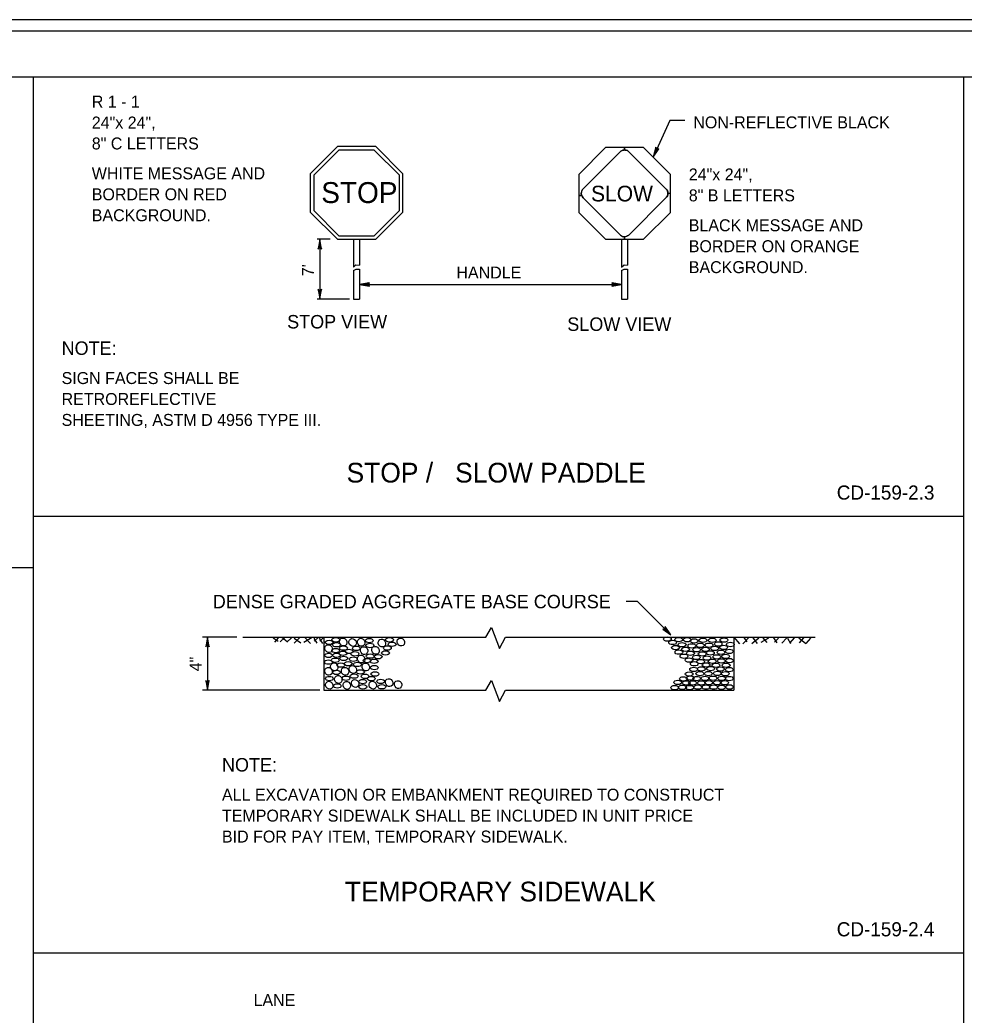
# Model space of a CAD drawing. Extents: x 499940 to 501012, y 499990 to 500649.
# Drawn here: x 500335 to 500650.7, y 500316.4 to 500649.2 of the extents above; entities that cross this region are included whole.
import ezdxf

# ---------------------------------------------------------------- set-up
doc = ezdxf.new("R2010")
doc.units = 0
for name, color, linetype in [('1', 7, 'Continuous'), ('10', 7, 'Continuous'), ('24', 7, 'Continuous'), ('3', 7, 'Continuous'), ('41', 7, 'Continuous'), ('5', 7, 'Continuous'), ('56', 7, 'Continuous'), ('57', 7, 'Continuous'), ('60', 7, 'Continuous')]:
    doc.layers.add(name, color=color, linetype=linetype)

msp = doc.modelspace()

# ---------------------------------------------------------------- linework, layer by layer
at = {"layer": '1'}
for p, q in [((500990, 500630), (500000, 500630)), ((500407.51, 500442.8), (500396.01, 500442.8)), ((500397.71, 500442.8), (500397.71, 500425.08)), ((500409.5, 500442.8), (500490.79, 500442.8)), ((500419.72, 500442.59), (500421.34, 500441.4)), ((500421.34, 500442.59), (500420.1, 500441.14)), ((500423.6, 500442.64), (500422.04, 500441.19)), ((500422.73, 500442.64), (500424.4, 500441.35)), ((500425.85, 500442.59), (500424.24, 500441.08)), ((500428.7, 500442.75), (500426.66, 500440.81)), ((500426.71, 500442.48), (500428.87, 500440.92)), ((500432.68, 500442.64), (500429.89, 500441.03)), ((500430.32, 500442.59), (500432.2, 500440.65)), ((500433.28, 500442.48), (500434.3, 500440.76)), ((500434.62, 500442.59), (500433.33, 500441.4)), ((500435, 500442.48), (500436.13, 500440.65)), ((500436.66, 500442.8), (500435.32, 500441.46)), ((500436.66, 500442.8), (500436.66, 500425.08)), ((500497.31, 500442.8), (500600.84, 500442.8)), ((500573.67, 500442.8), (500573.67, 500425.08)), ((500573.67, 500442.8), (500575.59, 500440.59)), ((500578.56, 500442.58), (500576.66, 500440.51)), ((500577.04, 500442.65), (500578.03, 500441.2)), ((500582.08, 500442.5), (500579.71, 500440.51)), ((500580.01, 500442.58), (500581.46, 500440.67)), ((500585.28, 500442.5), (500582.76, 500440.97)), ((500583.3, 500442.65), (500584.75, 500440.97)), ((500586.96, 500442.58), (500588.11, 500440.9)), ((500588.64, 500442.42), (500587.27, 500441.12)), ((500591.46, 500442.58), (500589.78, 500440.82)), ((500591.62, 500442.5), (500592.61, 500440.67)), ((500593.83, 500442.58), (500592.38, 500440.9)), ((500595.43, 500442.58), (500597.72, 500440.67)), ((500597.04, 500442.58), (500595.59, 500440.9)), ((500599.33, 500442.5), (500597.8, 500440.67)), ((500435.32, 500425.08), (500396.01, 500425.08)), ((500436.66, 500425.08), (500490.79, 500425.08)), ((500497.31, 500425.08), (500573.67, 500425.08))]:
    msp.add_line(p, q, dxfattribs=at)
for points in [[(499956.44, 500645.46), (500590.04, 500645.46), (501001.61, 500645.46)], [(500490.79, 500442.8), (500492.71, 500446), (500495.29, 500439.03), (500497.31, 500442.8)], [(500490.79, 500425.08), (500492.71, 500428.29), (500495.29, 500421.31), (500497.31, 500425.08)]]:
    msp.add_lwpolyline(points, dxfattribs=at)
for centre in [(500438.4, 500441.05), (500440.61, 500441.9), (500440.84, 500440.24), (500451.8, 500441.66), (500452.01, 500440.01), (500458.56, 500441.9), (500459.42, 500440.41), (500551.47, 500442.15), (500553.23, 500441.02), (500555.27, 500441.98), (500556.4, 500440.28), (500558.1, 500441.92), (500559.62, 500439.89), (500560.42, 500441.53), (500562.51, 500440.06), (500563.36, 500441.75), (500565.4, 500440.11), (500566.47, 500441.75), (500568.51, 500440.51), (500570.38, 500441.81), (500572.53, 500440.34), (500438.18, 500436.69), (500440.55, 500438.29), (500440.84, 500436.75), (500443.03, 500437.4), (500443.15, 500439.12), (500445.05, 500438.05), (500447, 500437.22), (500447.48, 500439.06), (500452.1, 500436.45), (500457.22, 500437.53), (500457.85, 500439.17), (500554.19, 500439.32), (500555.27, 500437.79), (500557.02, 500436.43), (500557.53, 500438.75), (500559.17, 500437.4), (500561.26, 500438.58), (500563.13, 500437.17), (500564.21, 500438.7), (500565.85, 500437.51), (500567.32, 500439.04), (500569.41, 500437.74), (500570.26, 500439.38), (500572.19, 500438.02), (500438.14, 500434.44), (500440.43, 500435.09), (500442.28, 500433.44), (500443.27, 500435.68), (500444.75, 500433.9), (500446.47, 500435.44), (500447.83, 500433.66), (500451.03, 500434.97), (500453.42, 500434.73), (500454.77, 500436.27), (500558.72, 500435.13), (500560.47, 500433.89), (500561.15, 500436.04), (500562.57, 500434.62), (500564.43, 500433.49), (500564.72, 500435.81), (500566.47, 500434.74), (500567.72, 500433.38), (500568, 500436.21), (500569.53, 500434.85), (500570.94, 500436.38), (500571.11, 500433.38), (500572.24, 500434.96), (500440.85, 500431.03), (500446.74, 500429.76), (500448.84, 500431.18), (500453.46, 500432.6), (500453.7, 500430.48), (500558.77, 500430.44), (500560.25, 500432.02), (500562.34, 500430.6), (500562.85, 500432.19), (500565.17, 500430.6), (500565.91, 500432.3), (500568.17, 500430.66), (500569.24, 500432.13), (500570.83, 500430.55), (500572.19, 500431.96), (500438.44, 500428.96), (500441.09, 500426.48), (500444.02, 500429.08), (500449.55, 500427.92), (500450.38, 500429.7), (500452.45, 500428.92), (500455.62, 500428), (500554.93, 500427.66), (500556.85, 500428.85), (500557.81, 500427.49), (500559.11, 500429.13), (500559.91, 500427.49), (500561.26, 500428.96), (500562.79, 500427.49), (500564.09, 500429.02), (500565.34, 500427.55), (500566.7, 500429.08), (500568.11, 500427.55), (500569.64, 500429.02), (500570.6, 500427.55), (500572.19, 500428.96), (500449.64, 500426.19), (500456.01, 500426.2), (500553.91, 500425.91), (500556.51, 500426.02), (500558.94, 500425.96), (500561.66, 500426.08), (500564.38, 500426.08), (500566.92, 500426.08), (500569.58, 500426.02), (500572.24, 500426.13)]:
    msp.add_ellipse(centre, major_axis=(1.32, 0), ratio=0.551788, dxfattribs=at)
at = {"layer": '10'}
for p, q in [((500339.52, 500000), (500339.52, 500630)), ((500650.61, 500104.92), (500650.61, 500630)), ((500339.52, 500483.27), (500650.61, 500483.27)), ((500000, 500466.05), (500339.52, 500466.05)), ((500339.52, 500337.26), (500650.61, 500337.26))]:
    msp.add_line(p, q, dxfattribs=at)
at = {"layer": '24'}
for points in [[(500546.76, 500603.31), (500548.66, 500606.1), (500547.8, 500605.62), (500547.59, 500606.56), (500546.76, 500603.31), (500546.84, 500603.51), (500548.58, 500606.03), (500547.76, 500605.56), (500547.57, 500606.42), (500546.88, 500603.62), (500546.94, 500603.72), (500548.42, 500605.88), (500547.76, 500605.55), (500547.59, 500606.27), (500546.96, 500603.77), (500546.99, 500603.87), (500548.29, 500605.76), (500547.75, 500605.52), (500547.57, 500606.1), (500547.12, 500604.17), (500547.2, 500604.34), (500548.14, 500605.64), (500547.75, 500605.49), (500547.58, 500605.92), (500547.23, 500604.36), (500547.31, 500604.52), (500547.99, 500605.52), (500547.68, 500605.4), (500547.58, 500605.72), (500547.37, 500604.67), (500547.45, 500604.82), (500547.87, 500605.41), (500547.68, 500605.37), (500547.59, 500605.62), (500547.48, 500604.9), (500547.77, 500605.28), (500547.62, 500605.27), (500547.59, 500605.51), (500547.51, 500605.02), (500547.7, 500605.26), (500547.56, 500605.19), (500547.56, 500605.35), (500547.59, 500605.17), (500547.64, 500605.24)], [(500435.26, 500575.82), (500434.67, 500572.5), (500435.26, 500573.29), (500435.84, 500572.51), (500435.26, 500575.82), (500435.27, 500575.6), (500434.72, 500572.59), (500435.27, 500573.35), (500435.79, 500572.65), (500435.28, 500575.48), (500435.26, 500575.37), (500434.8, 500572.79), (500435.27, 500573.37), (500435.72, 500572.77), (500435.26, 500575.32), (500435.28, 500575.21), (500434.87, 500572.95), (500435.26, 500573.39), (500435.67, 500572.94), (500435.28, 500574.89), (500435.28, 500574.7), (500434.95, 500573.12), (500435.25, 500573.43), (500435.58, 500573.1), (500435.26, 500574.67), (500435.25, 500574.49), (500435.05, 500573.3), (500435.28, 500573.53), (500435.51, 500573.28), (500435.26, 500574.33), (500435.24, 500574.16), (500435.11, 500573.45), (500435.27, 500573.56), (500435.45, 500573.37), (500435.26, 500574.07), (500435.15, 500573.61), (500435.28, 500573.67), (500435.4, 500573.47), (500435.28, 500573.95), (500435.2, 500573.65), (500435.3, 500573.78), (500435.36, 500573.63), (500435.27, 500573.78), (500435.25, 500573.7)], [(500448.56, 500560.71), (500451.83, 500560.14), (500451.05, 500560.71), (500451.82, 500561.28), (500448.56, 500560.71), (500448.78, 500560.72), (500451.74, 500560.18), (500450.99, 500560.72), (500451.68, 500561.24), (500448.89, 500560.73), (500449, 500560.71), (500451.54, 500560.26), (500450.97, 500560.72), (500451.56, 500561.17), (500449.05, 500560.71), (500449.16, 500560.73), (500451.38, 500560.33), (500450.95, 500560.71), (500451.39, 500561.11), (500449.48, 500560.73), (500449.66, 500560.73), (500451.22, 500560.41), (500450.91, 500560.71), (500451.24, 500561.03), (500449.69, 500560.71), (500449.87, 500560.7), (500451.04, 500560.5), (500450.81, 500560.73), (500451.06, 500560.96), (500450.03, 500560.71), (500450.2, 500560.7), (500450.9, 500560.56), (500450.78, 500560.72), (500450.97, 500560.9), (500450.28, 500560.71), (500450.74, 500560.61), (500450.67, 500560.73), (500450.87, 500560.86), (500450.4, 500560.73), (500450.7, 500560.66), (500450.57, 500560.75), (500450.72, 500560.81), (500450.57, 500560.72), (500450.65, 500560.71)], [(500536.18, 500560.71), (500532.91, 500561.29), (500533.69, 500560.71), (500532.92, 500560.15), (500536.18, 500560.71), (500535.96, 500560.71), (500533, 500561.25), (500533.75, 500560.71), (500533.05, 500560.19), (500535.85, 500560.7), (500535.74, 500560.71), (500533.2, 500561.17), (500533.77, 500560.71), (500533.18, 500560.26), (500535.69, 500560.72), (500535.58, 500560.7), (500533.36, 500561.1), (500533.79, 500560.72), (500533.35, 500560.32), (500535.26, 500560.7), (500535.08, 500560.7), (500533.52, 500561.02), (500533.82, 500560.72), (500533.5, 500560.4), (500535.04, 500560.71), (500534.87, 500560.73), (500533.7, 500560.92), (500533.92, 500560.7), (500533.68, 500560.47), (500534.71, 500560.71), (500534.54, 500560.73), (500533.84, 500560.87), (500533.96, 500560.71), (500533.77, 500560.53), (500534.46, 500560.72), (500534, 500560.82), (500534.07, 500560.7), (500533.87, 500560.57), (500534.34, 500560.7), (500534.04, 500560.77), (500534.17, 500560.67), (500534.02, 500560.62), (500534.17, 500560.71), (500534.09, 500560.72)], [(500435.26, 500555.83), (500435.84, 500559.11), (500435.26, 500558.33), (500434.69, 500559.09), (500435.26, 500555.83), (500435.26, 500556.05), (500435.8, 500559.02), (500435.25, 500558.27), (500434.74, 500558.96), (500435.25, 500556.17), (500435.26, 500556.28), (500435.71, 500558.82), (500435.25, 500558.25), (500434.81, 500558.83), (500435.26, 500556.33), (500435.25, 500556.44), (500435.65, 500558.66), (500435.26, 500558.23), (500434.86, 500558.67), (500435.24, 500556.75), (500435.25, 500556.94), (500435.56, 500558.49), (500435.27, 500558.19), (500434.94, 500558.52), (500435.26, 500556.97), (500435.27, 500557.15), (500435.47, 500558.31), (500435.24, 500558.09), (500435.02, 500558.33), (500435.26, 500557.31), (500435.28, 500557.47), (500435.41, 500558.17), (500435.25, 500558.06), (500435.08, 500558.25), (500435.26, 500557.56), (500435.37, 500558.01), (500435.25, 500557.95), (500435.12, 500558.15), (500435.24, 500557.67), (500435.32, 500557.97), (500435.22, 500557.85), (500435.16, 500557.99), (500435.25, 500557.85), (500435.27, 500557.92)], [(500397.71, 500442.8), (500397.13, 500439.52), (500397.71, 500440.3), (500398.28, 500439.54), (500397.71, 500442.8), (500397.72, 500442.58), (500397.17, 500439.61), (500397.72, 500440.37), (500398.24, 500439.67), (500397.73, 500442.46), (500397.71, 500442.35), (500397.26, 500439.81), (500397.72, 500440.38), (500398.16, 500439.8), (500397.71, 500442.3), (500397.73, 500442.19), (500397.33, 500439.97), (500397.71, 500440.41), (500398.11, 500439.97), (500397.73, 500441.88), (500397.73, 500441.69), (500397.41, 500440.14), (500397.7, 500440.44), (500398.03, 500440.12), (500397.71, 500441.66), (500397.7, 500441.49), (500397.5, 500440.32), (500397.73, 500440.54), (500397.95, 500440.3), (500397.71, 500441.32), (500397.69, 500441.16), (500397.56, 500440.46), (500397.72, 500440.57), (500397.89, 500440.38), (500397.71, 500441.07), (500397.6, 500440.62), (500397.73, 500440.68), (500397.85, 500440.48), (500397.73, 500440.96), (500397.65, 500440.66), (500397.75, 500440.78), (500397.81, 500440.64), (500397.72, 500440.78), (500397.7, 500440.71)], [(500397.71, 500425.08), (500398.29, 500428.35), (500397.71, 500427.57), (500397.14, 500428.34), (500397.71, 500425.08), (500397.7, 500425.3), (500398.25, 500428.26), (500397.7, 500427.51), (500397.19, 500428.2), (500397.69, 500425.41), (500397.71, 500425.52), (500398.16, 500428.06), (500397.7, 500427.49), (500397.26, 500428.08), (500397.71, 500425.57), (500397.69, 500425.68), (500398.1, 500427.9), (500397.71, 500427.47), (500397.31, 500427.91), (500397.69, 500426), (500397.69, 500426.18), (500398.01, 500427.74), (500397.72, 500427.44), (500397.39, 500427.76), (500397.71, 500426.22), (500397.72, 500426.39), (500397.92, 500427.56), (500397.69, 500427.34), (500397.47, 500427.58), (500397.71, 500426.55), (500397.73, 500426.72), (500397.86, 500427.42), (500397.7, 500427.3), (500397.53, 500427.49), (500397.71, 500426.8), (500397.82, 500427.26), (500397.69, 500427.19), (500397.57, 500427.39), (500397.69, 500426.92), (500397.77, 500427.22), (500397.67, 500427.09), (500397.61, 500427.24), (500397.7, 500427.09), (500397.72, 500427.17)]]:
    msp.add_lwpolyline(points, dxfattribs=at)
at = {"layer": '3'}
for points in [[(500530.83, 500606.48), (500521.85, 500597.5), (500521.85, 500584.8), (500530.83, 500575.82), (500543.53, 500575.82), (500552.51, 500584.8), (500552.51, 500597.5), (500543.53, 500606.48), (500530.83, 500606.48)], [(500535.94, 500605.24), (500523.12, 500592.42)], [(500551.11, 500592.55), (500538.69, 500604.96)], [(500523.3, 500589.71), (500535.79, 500577.22)], [(500538.57, 500577.22), (500551.09, 500589.74)], [(500552.67, 500443.55), (500541.52, 500454.69), (500537.7, 500454.69)]]:
    msp.add_lwpolyline(points, dxfattribs=at)
for centre in [(500438.22, 500438.96), (500443.07, 500441.19), (500446.24, 500441.01), (500449.12, 500441.1), (500456.02, 500440.82), (500462.36, 500441.19), (500450.06, 500438.3), (500453.88, 500438.4), (500440.09, 500432.89), (500449.12, 500435.51), (500450.62, 500432.8), (500438.16, 500431.34), (500443.7, 500431.39), (500446.3, 500431.99), (500438.41, 500426.75), (500441.44, 500428.66), (500444.28, 500426.65), (500447.07, 500427.31), (500452.95, 500426.75), (500458.44, 500427.59), (500461.43, 500426.93)]:
    msp.add_ellipse(centre, major_axis=(-0.73, 1.14), ratio=0.897616, dxfattribs=at)
at = {"layer": '41'}
msp.add_lwpolyline([(499939.98, 499990.18), (501000.54, 499990.18), (501000.54, 500649.16), (499939.98, 500649.16)], close=True, dxfattribs=at)
at = {"layer": '5'}
for p, q in [((500552.27, 500615.57), (500546.76, 500603.31)), ((500557.27, 500615.57), (500552.27, 500615.57)), ((500438.73, 500575.82), (500434.4, 500575.82)), ((500435.26, 500575.82), (500435.26, 500555.83)), ((500446.56, 500575.82), (500446.56, 500566.48)), ((500448.56, 500575.82), (500448.56, 500567.18)), ((500536.18, 500575.82), (500536.18, 500566.48)), ((500538.18, 500575.82), (500538.18, 500567.18)), ((500446.56, 500565.38), (500446.56, 500555.83)), ((500448.56, 500565.81), (500448.56, 500555.83)), ((500536.18, 500565.38), (500536.18, 500555.83)), ((500538.18, 500565.81), (500538.18, 500555.83)), ((500448.56, 500560.71), (500536.18, 500560.71)), ((500445.19, 500555.83), (500434.4, 500555.83)), ((500446.56, 500555.83), (500448.56, 500555.83)), ((500536.18, 500555.83), (500538.18, 500555.83))]:
    msp.add_line(p, q, dxfattribs=at)
for points in [[(500446.56, 500566.48), (500447.35, 500567.25), (500448.56, 500567.18)], [(500536.18, 500566.48), (500536.97, 500567.25), (500538.18, 500567.18)], [(500446.56, 500565.38), (500447.46, 500565.82), (500448.56, 500565.81)], [(500536.18, 500565.38), (500537.08, 500565.82), (500538.18, 500565.81)], [(500552.67, 500443.55), (500550.72, 500446.33), (500550.87, 500445.35), (500549.91, 500445.49), (500552.67, 500443.55), (500552.51, 500443.7), (500550.76, 500446.23), (500550.91, 500445.3), (500550.03, 500445.42), (500552.41, 500443.78), (500552.35, 500443.87), (500550.84, 500446.03), (500550.92, 500445.28), (500550.18, 500445.39), (500552.31, 500443.9), (500552.22, 500443.97), (500550.91, 500445.86), (500550.94, 500445.27), (500550.34, 500445.3), (500551.99, 500444.2), (500551.86, 500444.33), (500550.97, 500445.68), (500550.98, 500445.25), (500550.51, 500445.25), (500551.85, 500444.37), (500551.73, 500444.5), (500551.03, 500445.49), (500551.03, 500445.16), (500550.69, 500445.18), (500551.61, 500444.61), (500551.5, 500444.74), (500551.09, 500445.34), (500551.06, 500445.15), (500550.79, 500445.16), (500551.43, 500444.79), (500551.17, 500445.2), (500551.13, 500445.06), (500550.9, 500445.12), (500551.33, 500444.86), (500551.17, 500445.13), (500551.19, 500444.97), (500551.04, 500445.03), (500551.21, 500444.99), (500551.17, 500445.06)]]:
    msp.add_lwpolyline(points, dxfattribs=at)
for centre, start, end in [((500537.17, 500603.7), 39.6068, 128.4005), ((500524.66, 500591.19), 141.1852, 227.5027), ((500549.7, 500591.16), 314.4981, 44.5015), ((500537.17, 500578.64), 225.8715, 314.7969)]:
    msp.add_arc(centre, 1.98, start, end, dxfattribs=at)
at = {"layer": '56'}
msp.add_lwpolyline([(500441.14, 500606.82), (500432.06, 500597.74), (500432.06, 500584.9), (500441.14, 500575.82), (500453.98, 500575.82), (500463.06, 500584.9), (500463.06, 500597.74), (500453.98, 500606.82), (500441.14, 500606.82)], dxfattribs=at)
at = {"layer": '57'}
for p, q in [((500447.56, 500575.82), (500447.56, 500575.82)), ((500537.18, 500575.82), (500537.18, 500575.82))]:
    msp.add_line(p, q, dxfattribs=at)
at = {"layer": '60'}
for points in [[(500453.48, 500577.02), (500461.86, 500585.4), (500461.86, 500597.25), (500453.48, 500605.62), (500441.64, 500605.62), (500433.26, 500597.25), (500433.26, 500585.4), (500441.64, 500577.02)], [(500535.94, 500605.24), (500536.35, 500605.47), (500536.66, 500605.59), (500537.04, 500605.65), (500537.17, 500605.67), (500537.16, 500606.48), (500530.83, 500606.48), (500521.85, 500597.5), (500521.86, 500590.42), (500522.78, 500590.49), (500522.71, 500590.78), (500522.69, 500591.14), (500522.71, 500591.47), (500522.82, 500591.86), (500523, 500592.26), (500523.12, 500592.42)], [(500551.11, 500592.55), (500551.52, 500591.97), (500551.61, 500591.76), (500551.68, 500591.45), (500551.68, 500591.16), (500552.51, 500591.25), (500552.51, 500597.5), (500543.53, 500606.48), (500537.16, 500606.48), (500537.17, 500605.67), (500537.41, 500605.65), (500537.63, 500605.61), (500538.01, 500605.47), (500538.24, 500605.36), (500538.44, 500605.2), (500538.69, 500604.96)], [(500523.3, 500589.71), (500523.08, 500589.99), (500522.93, 500590.3), (500522.78, 500590.49), (500521.86, 500590.42), (500521.85, 500584.8), (500530.83, 500575.82), (500537.18, 500575.82), (500537.17, 500576.66), (500536.95, 500576.66), (500536.68, 500576.69), (500536.37, 500576.75), (500536.01, 500576.96), (500535.79, 500577.22)], [(500538.57, 500577.22), (500538.41, 500577.07), (500538.16, 500576.93), (500537.76, 500576.78), (500537.4, 500576.69), (500537.17, 500576.66), (500537.18, 500575.82), (500543.53, 500575.82), (500552.51, 500584.8), (500552.51, 500591.25), (500551.68, 500591.16), (500551.64, 500590.87), (500551.6, 500590.62), (500551.49, 500590.37), (500551.35, 500590.04), (500551.09, 500589.74)]]:
    msp.add_lwpolyline(points, close=True, dxfattribs=at)

# ---------------------------------------------------------------- texts
at = {"layer": '1'}
msp.add_text('TEMPORARY SIDEWALK', height=6.6001, dxfattribs=at).set_placement((500443.65, 500354.44))
at = {"layer": '3'}
msp.add_text('LANE', height=4, dxfattribs=at).set_placement((500413.11, 500319.46))
at = {"layer": '5'}
for s, height, p in [('R 1 - 1', 4, (500359.02, 500619.85)), ('24"x 24",', 4, (500359.02, 500612.85)), ('NON-REFLECTIVE BLACK', 4, (500560.14, 500612.91)), ('8" C LETTERS', 4, (500359.02, 500605.85)), ('WHITE MESSAGE AND ', 4, (500359.02, 500595.85)), ('24"x 24",', 4, (500558.63, 500595.5)), ('SLOW', 5.25, (500525.96, 500588.47)), ('BORDER ON RED ', 4, (500359.02, 500588.85)), ('8" B LETTERS', 4, (500558.63, 500588.5)), ('BACKGROUND.', 4, (500359.02, 500581.85)), ('BLACK MESSAGE AND ', 4, (500558.63, 500578.5)), ('BORDER ON ORANGE ', 4, (500558.63, 500571.5)), ('BACKGROUND.', 4, (500558.63, 500564.5)), ('HANDLE', 4, (500480.93, 500562.71)), ('STOP VIEW', 4.5, (500424.34, 500546)), ('SLOW VIEW', 4.5, (500518.01, 500545.19)), ('NOTE:', 4.5, (500348.93, 500537.17)), ('SIGN FACES SHALL BE', 4, (500348.93, 500527.42)), ('RETROREFLECTIVE', 4, (500348.93, 500520.42)), ('SHEETING, ASTM D 4956 TYPE III.', 4, (500348.93, 500513.42)), ('STOP /   SLOW PADDLE', 6.6001, (500444.21, 500494.49)), ('CD-159-2.3', 4.724, (500608.11, 500488.78)), ('DENSE GRADED AGGREGATE BASE COURSE', 4.5, (500399.47, 500452.44)), ('NOTE:', 4.5, (500402.55, 500397.88)), ('ALL EXCAVATION OR EMBANKMENT REQUIRED TO CONSTRUCT', 4, (500402.55, 500388.13)), ('TEMPORARY SIDEWALK SHALL BE INCLUDED IN UNIT PRICE', 4, (500402.55, 500381.13)), ('BID FOR PAY ITEM, TEMPORARY SIDEWALK.', 4, (500402.55, 500374.13)), ('CD-159-2.4', 4.724, (500608.1, 500342.77))]:
    msp.add_text(s, height=height, dxfattribs=at).set_placement(p)
for s, p in [("7'", (500433.29, 500563.47)), ('4"', (500395.71, 500431.37))]:
    msp.add_text(s, height=4, rotation=90, dxfattribs=at).set_placement(p)
at = {"layer": '60'}
msp.add_text('STOP', height=7, dxfattribs=at).set_placement((500435.75, 500587.93))

doc.saveas('drawing.dxf')
